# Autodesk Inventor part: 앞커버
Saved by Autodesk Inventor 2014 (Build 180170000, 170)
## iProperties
Created: 2025-06
Part Number: 앞커버
Material: 일반
Document SubType Name: Modeling
Designer: dg
Density: 1 g/cm^3
Appearance: 기본값
Author: dg
Author: jhkim
Creation Date: 2025-05-23
Sending System: Autodesk Inventor 2026
Preprocessor: ST-DEVELOPER v20.1
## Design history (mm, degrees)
node "앞커버1"
node "솔리드1"
node "기준1"
